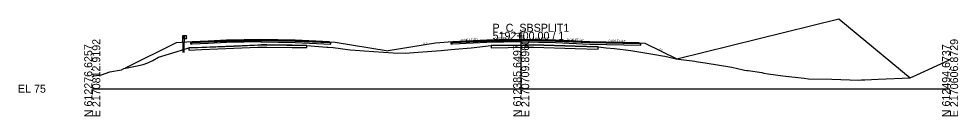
# Model space of a CAD drawing. Extents: x -26 to 1303, y -3010 to 12033.
# Drawn here: x -25.7 to 302.8, y 10490.3 to 10524.6 of the extents above; entities that cross this region are included whole.
import ezdxf

# ---------------------------------------------------------------- set-up
doc = ezdxf.new("R2010")
doc.units = 0
for name, color, linetype in [('RD_GPK_XS_Cell', 7, 'Continuous'), ('RD_PD_Final_TrvlWay', 7, 'Continuous'), ('RD_Sketch10', 7, 'Continuous'), ('RD_XS_Base', 7, 'Continuous'), ('RD_XS_ExGround', 7, 'Continuous'), ('RD_XS_ExPaveRet', 7, 'Continuous'), ('RD_XS_GR', 7, 'Continuous'), ('RD_XS_Greenside', 7, 'Continuous'), ('RD_XS_Pave', 7, 'Continuous'), ('RD_XS_PaveOvlay_CP', 7, 'Continuous'), ('RD_XS_TieSlope', 7, 'Continuous'), ('RD_XS_TX_Elev_EX', 7, 'Continuous'), ('RD_XS_TX_Elev_PR', 7, 'Continuous'), ('RD_XS_TX_Slope', 7, 'Continuous')]:
    doc.layers.add(name, color=color, linetype=linetype)

msp = doc.modelspace()

# ---------------------------------------------------------------- linework, layer by layer
at = {"layer": 'RD_GPK_XS_Cell'}
for p, q in [((150, 10500), (150, 10520)), ((0, 10500), (150, 10500)), ((150, 10500), (300, 10500))]:
    msp.add_line(p, q, dxfattribs=at)
at = {"layer": 'RD_PD_Final_TrvlWay'}
msp.add_lwpolyline([(32.13, 10512.68), (32.13, 10516.28), (31.63, 10516.24), (31.63, 10512.68)], dxfattribs=at)
at = {"layer": 'RD_Sketch10'}
msp.add_lwpolyline([(204.39, 10510.46), (261.07, 10524.58), (286.02, 10503.83)], dxfattribs=at)
at = {"layer": 'RD_XS_Base'}
for p, q in [((34.96, 10516.19), (40.51, 10516.41)), ((40.51, 10516.41), (46.96, 10516.67)), ((46.96, 10516.67), (53.12, 10516.79)), ((53.12, 10516.79), (58.96, 10516.91)), ((58.96, 10516.41), (53.12, 10516.29)), ((58.96, 10517), (58.96, 10517.07)), ((58.96, 10517.07), (58.96, 10516.76)), ((58.96, 10516.91), (58.96, 10517.07)), ((58.96, 10517.07), (58.96, 10516.41)), ((58.96, 10516.91), (58.96, 10517)), ((58.96, 10516.91), (58.96, 10516.68)), ((58.96, 10516.91), (58.96, 10516.41)), ((70.96, 10516.67), (58.96, 10516.91)), ((58.96, 10516.91), (58.96, 10516.91)), ((58.96, 10516.76), (58.96, 10516.41)), ((58.96, 10516.68), (58.96, 10516.41)), ((58.96, 10516.41), (58.96, 10516.41)), ((58.96, 10516.41), (58.96, 10516.41)), ((58.96, 10516.41), (70.96, 10516.17)), ((82.96, 10516.19), (70.96, 10516.67)), ((72.96, 10516.59), (72.96, 10516.59)), ((126, 10516.19), (138, 10516.67)), ((136, 10516.59), (136, 10516.59)), ((138, 10516.67), (150, 10516.91)), ((150, 10516.41), (138, 10516.17)), ((150, 10516.91), (150, 10517.07)), ((150, 10517.07), (150, 10516.41)), ((150, 10516.91), (150, 10516.91)), ((162, 10516.67), (150, 10516.91)), ((150, 10516.91), (150, 10516.91)), ((150, 10516.91), (150, 10516.41)), ((150, 10516.41), (150, 10516.41)), ((150, 10516.41), (162, 10516.17)), ((150, 10516.41), (150, 10516.41)), ((174, 10516.19), (162, 10516.67)), ((162, 10516.67), (162, 10516.67)), ((34.46, 10516.17), (34.68, 10516.18)), ((34.46, 10515.89), (34.46, 10516.17)), ((34.46, 10515.67), (34.46, 10515.89)), ((34.68, 10515.68), (34.46, 10515.67)), ((34.68, 10516.18), (34.96, 10516.19)), ((34.96, 10515.69), (34.68, 10515.68)), ((40.51, 10515.91), (34.96, 10515.69)), ((46.96, 10516.17), (40.51, 10515.91)), ((53.12, 10516.29), (46.96, 10516.17)), ((70.96, 10516.17), (83.46, 10515.67)), ((72.96, 10516.09), (72.96, 10516.09)), ((83.46, 10516.17), (82.96, 10516.19)), ((82.96, 10516.19), (82.96, 10516.19)), ((83.46, 10515.67), (83.46, 10516.17)), ((83.46, 10516.17), (83.46, 10516.17)), ((83.46, 10515.67), (83.46, 10515.67)), ((83.46, 10515.67), (83.46, 10515.67)), ((125.5, 10516.17), (126, 10516.19)), ((125.5, 10515.67), (125.5, 10516.17)), ((125.5, 10516.17), (125.5, 10516.17)), ((126, 10515.69), (125.5, 10515.67)), ((125.5, 10515.67), (125.5, 10515.67)), ((125.5, 10515.67), (125.5, 10515.67)), ((126, 10516.19), (126, 10516.19)), ((138, 10516.17), (126, 10515.69)), ((126, 10515.69), (126, 10515.69)), ((136, 10516.09), (136, 10516.09)), ((162, 10516.17), (162, 10516.17)), ((162, 10516.17), (174, 10515.69)), ((191.3, 10515.85), (174, 10516.19)), ((174, 10516.19), (174, 10516.19)), ((174, 10515.69), (174, 10515.69)), ((174, 10515.69), (191.8, 10515.34)), ((191.8, 10515.84), (191.3, 10515.85)), ((191.3, 10515.85), (191.3, 10515.85)), ((191.8, 10515.34), (191.8, 10515.84)), ((191.8, 10515.84), (191.8, 10515.84)), ((191.8, 10515.34), (191.8, 10515.34)), ((191.8, 10515.34), (191.8, 10515.34))]:
    msp.add_line(p, q, dxfattribs=at)
at = {"layer": 'RD_XS_ExGround'}
msp.add_lwpolyline([(0, 10504.22), (0.53, 10504.47), (3.21, 10504.91), (6.16, 10505.96), (10.24, 10506.67), (11.05, 10507.06), (15.14, 10507.95), (17.8, 10508.48), (19.41, 10509.13), (21.13, 10509.93), (23.18, 10511.04), (29.4, 10512.89), (33.81, 10514.33), (49.47, 10514.98), (59.16, 10515.39), (61.08, 10515.36), (75.08, 10515.17), (82.06, 10514.64), (82.48, 10514.61), (84.23, 10514.49), (86.82, 10514.07), (90.21, 10513.69), (92, 10513.5), (95.09, 10513.25), (105.19, 10512.54), (109.39, 10512.45), (113.99, 10512.87), (122, 10513.47), (123.02, 10513.5), (126.8, 10513.87), (132.55, 10514.4), (139.47, 10515.14), (151.38, 10515.32), (154.34, 10515.37), (168.93, 10514.92), (176.95, 10514.67), (179.7, 10514.38), (182.62, 10514.07), (188.36, 10513.47), (197.44, 10511.91), (199.42, 10511.55), (200.25, 10511.43), (203.78, 10510.56), (204.06, 10510.5), (210.7, 10509.64), (211.15, 10509.58), (211.92, 10509.44), (214.4, 10509.06), (223.7, 10507.52), (227.69, 10506.65), (228.09, 10506.54), (228.88, 10506.43), (229.43, 10506.34), (234.12, 10505.67), (234.88, 10505.5), (236.33, 10505.27), (241.55, 10504.49), (248.91, 10503.67), (250.54, 10503.5), (258.65, 10503.31), (268.1, 10503.05), (268.99, 10503.07), (270.22, 10503.14), (274.79, 10503.32), (286.02, 10503.83), (288.32, 10504.81), (298.31, 10509.39), (299.32, 10509.88), (300, 10510.21)], dxfattribs=at)
at = {"layer": 'RD_XS_ExPaveRet'}
for points in [[(61.08, 10515.36), (59.42, 10515.39), (59.16, 10515.39), (57.95, 10515.34), (49.47, 10514.98), (38.35, 10514.52), (33.81, 10514.33), (33.81, 10514), (33.81, 10513.58), (38.35, 10513.77), (49.47, 10514.23), (57.95, 10514.59), (59.16, 10514.64), (59.42, 10514.64), (61.08, 10514.61), (69.93, 10514.49), (75.08, 10514.42), (75.08, 10514.72), (75.08, 10515.17), (69.93, 10515.24), (61.08, 10515.36)], [(61.08, 10515.36), (59.42, 10515.39), (59.16, 10515.39), (57.95, 10515.34), (49.47, 10514.98), (38.35, 10514.52), (33.81, 10514.33), (33.81, 10514), (33.81, 10513.58), (38.35, 10513.77), (49.47, 10514.23), (57.95, 10514.59), (59.16, 10514.64), (59.42, 10514.64), (61.08, 10514.61), (69.93, 10514.49), (75.08, 10514.42), (75.08, 10514.72), (75.08, 10515.17), (69.93, 10515.24), (61.08, 10515.36)], [(176.95, 10514.67), (168.93, 10514.92), (168.93, 10514.92), (154.34, 10515.37), (154.34, 10515.37), (154.34, 10515.37), (154.34, 10515.37), (151.38, 10515.32), (151.38, 10515.32), (139.47, 10515.14), (139.47, 10515.14), (139.47, 10514.39), (151.38, 10514.57), (151.38, 10514.57), (154.34, 10514.62), (154.34, 10514.62), (154.34, 10514.62), (154.34, 10514.62), (168.93, 10514.17), (168.93, 10514.17), (176.95, 10513.92), (176.95, 10513.92), (176.95, 10513.92), (176.95, 10514.67), (176.95, 10514.67)], [(176.95, 10514.67), (168.93, 10514.92), (154.34, 10515.37), (151.38, 10515.32), (139.47, 10515.14), (139.47, 10514.39), (151.38, 10514.57), (154.34, 10514.62), (168.93, 10514.17), (176.95, 10513.92), (176.95, 10514.67)]]:
    msp.add_lwpolyline(points, dxfattribs=at)
at = {"layer": 'RD_XS_GR'}
for p, q in [((31.63, 10516.24), (31.63, 10518.68)), ((31.63, 10518.68), (31.88, 10518.68)), ((31.88, 10518.68), (32.13, 10518.68)), ((32.13, 10518.68), (32.13, 10516.28)), ((32.13, 10517.51), (32.13, 10518.68)), ((32.13, 10518.68), (32.79, 10518.68)), ((32.79, 10517.51), (32.13, 10517.51)), ((32.79, 10518.68), (32.79, 10517.51)), ((32.95, 10518.51), (32.79, 10518.68)), ((32.79, 10518.68), (32.79, 10518.01)), ((32.79, 10518.09), (32.91, 10518.22)), ((32.95, 10517.93), (32.79, 10518.09)), ((32.79, 10518.01), (32.79, 10517.51)), ((32.79, 10517.51), (32.91, 10517.64)), ((32.91, 10518.22), (33.07, 10518.39)), ((32.91, 10517.64), (33.07, 10517.8)), ((33.07, 10518.39), (32.95, 10518.51)), ((33.07, 10517.8), (32.95, 10517.93)), ((32.13, 10516.28), (31.63, 10516.24))]:
    msp.add_line(p, q, dxfattribs=at)
at = {"layer": 'RD_XS_Greenside'}
for p, q in [((84.96, 10516.35), (103.44, 10513.27)), ((29.32, 10516.06), (11.52, 10507.16)), ((120, 10516.03), (103.44, 10513.27)), ((193.3, 10516), (204.39, 10510.46))]:
    msp.add_line(p, q, dxfattribs=at)
at = {"layer": 'RD_XS_Pave'}
for p, q in [((40.51, 10516.73), (34.96, 10516.51)), ((40.51, 10516.57), (34.96, 10516.35)), ((34.96, 10516.35), (40.51, 10516.57)), ((34.96, 10516.51), (34.96, 10516.42)), ((34.96, 10516.42), (34.96, 10516.35)), ((34.96, 10516.19), (40.51, 10516.41)), ((34.96, 10516.35), (34.96, 10516.26)), ((46.96, 10516.99), (40.51, 10516.73)), ((46.96, 10516.83), (40.51, 10516.57)), ((40.51, 10516.57), (46.96, 10516.83)), ((40.51, 10516.41), (46.96, 10516.67)), ((53.12, 10517.11), (46.96, 10516.99)), ((53.12, 10516.95), (46.96, 10516.83)), ((46.96, 10516.83), (53.12, 10516.95)), ((46.96, 10516.67), (53.12, 10516.79)), ((58.96, 10517.23), (53.12, 10517.11)), ((58.96, 10517.07), (53.12, 10516.95)), ((53.12, 10516.95), (58.96, 10517.07)), ((53.12, 10516.79), (58.96, 10516.91)), ((70.96, 10516.99), (58.96, 10517.23)), ((58.96, 10517), (58.96, 10517.07)), ((58.96, 10517.07), (58.96, 10517)), ((58.96, 10516.91), (58.96, 10517.07)), ((58.96, 10517.07), (70.96, 10516.83)), ((70.96, 10516.83), (58.96, 10517.07)), ((58.96, 10517.07), (58.96, 10516.91)), ((58.96, 10516.91), (58.96, 10517)), ((58.96, 10517), (58.96, 10516.91)), ((58.96, 10516.91), (58.96, 10516.91)), ((58.96, 10516.91), (58.96, 10516.91)), ((58.96, 10516.91), (70.96, 10516.67)), ((82.96, 10516.51), (70.96, 10516.99)), ((70.96, 10516.83), (82.96, 10516.35)), ((82.96, 10516.35), (70.96, 10516.83)), ((70.96, 10516.67), (82.96, 10516.19)), ((72.96, 10516.91), (72.96, 10516.91)), ((72.96, 10516.75), (72.96, 10516.75)), ((72.96, 10516.75), (72.96, 10516.75)), ((72.96, 10516.59), (72.96, 10516.59)), ((82.96, 10516.35), (82.96, 10516.51)), ((82.96, 10516.51), (82.96, 10516.51)), ((82.96, 10516.35), (82.96, 10516.35)), ((82.96, 10516.35), (82.96, 10516.35)), ((82.96, 10516.19), (82.96, 10516.35)), ((82.96, 10516.35), (82.96, 10516.35)), ((138, 10516.99), (126, 10516.51)), ((138, 10516.83), (126, 10516.35)), ((126, 10516.35), (138, 10516.83)), ((126, 10516.19), (138, 10516.67)), ((126, 10516.51), (126, 10516.51)), ((126, 10516.51), (126, 10516.35)), ((126, 10516.35), (126, 10516.35)), ((126, 10516.35), (126, 10516.19)), ((126, 10516.35), (126, 10516.35)), ((126, 10516.35), (126, 10516.35)), ((136, 10516.91), (136, 10516.91)), ((136, 10516.75), (136, 10516.75)), ((136, 10516.75), (136, 10516.75)), ((136, 10516.59), (136, 10516.59)), ((150, 10517.23), (138, 10516.99)), ((150, 10517.07), (138, 10516.83)), ((138, 10516.83), (150, 10517.07)), ((138, 10516.67), (150, 10516.91)), ((162, 10516.99), (150, 10517.23)), ((150, 10516.91), (150, 10517.07)), ((150, 10517.07), (162, 10516.83)), ((162, 10516.83), (150, 10517.07)), ((150, 10517.07), (150, 10517.07)), ((150, 10517.07), (150, 10516.91)), ((150, 10516.91), (150, 10516.91)), ((150, 10516.91), (150, 10516.91)), ((150, 10516.91), (150, 10516.91)), ((150, 10516.91), (162, 10516.67)), ((174, 10516.51), (162, 10516.99)), ((162, 10516.99), (162, 10516.99)), ((162, 10516.83), (162, 10516.83)), ((162, 10516.83), (174, 10516.35)), ((174, 10516.35), (162, 10516.83)), ((162, 10516.83), (162, 10516.83)), ((162, 10516.67), (162, 10516.67)), ((162, 10516.67), (174, 10516.19)), ((191.3, 10516.16), (174, 10516.51)), ((174, 10516.51), (174, 10516.51)), ((174, 10516.35), (174, 10516.35)), ((174, 10516.35), (191.3, 10516)), ((191.3, 10516), (174, 10516.35)), ((174, 10516.35), (174, 10516.35)), ((34.96, 10516.26), (34.96, 10516.19)), ((82.96, 10516.19), (82.96, 10516.19)), ((82.96, 10516.19), (82.96, 10516.19)), ((126, 10516.19), (126, 10516.19)), ((126, 10516.19), (126, 10516.19)), ((174, 10516.19), (174, 10516.19)), ((174, 10516.19), (191.3, 10515.85)), ((191.3, 10516), (191.3, 10516.16)), ((191.3, 10516.16), (191.3, 10516.16)), ((191.3, 10516), (191.3, 10516)), ((191.3, 10516), (191.3, 10516)), ((191.3, 10515.85), (191.3, 10516)), ((191.3, 10516), (191.3, 10516)), ((191.3, 10515.85), (191.3, 10515.85)), ((191.3, 10515.85), (191.3, 10515.85))]:
    msp.add_line(p, q, dxfattribs=at)
at = {"layer": 'RD_XS_PaveOvlay_CP'}
for p, q in [((34.96, 10516.51), (46.96, 10516.99)), ((46.96, 10516.99), (58.96, 10517.23)), ((58.96, 10517.23), (70.96, 10516.99)), ((70.96, 10516.99), (82.96, 10516.51)), ((138, 10516.99), (126, 10516.51)), ((126, 10516.51), (126, 10516.51)), ((136, 10516.91), (136, 10516.91)), ((150, 10517.23), (138, 10516.99)), ((162, 10516.99), (150, 10517.23)), ((174, 10516.51), (162, 10516.99)), ((162, 10516.99), (162, 10516.99)), ((191.3, 10516.16), (174, 10516.51)), ((174, 10516.51), (174, 10516.51)), ((191.3, 10516.16), (191.3, 10516.16))]:
    msp.add_line(p, q, dxfattribs=at)
at = {"layer": 'RD_XS_TieSlope'}
for p, q in [((34.96, 10516.51), (29.32, 10516.06)), ((82.96, 10516.51), (84.96, 10516.35)), ((126, 10516.51), (120, 10516.03)), ((191.3, 10516.16), (193.3, 10516))]:
    msp.add_line(p, q, dxfattribs=at)

# ---------------------------------------------------------------- texts
at = {"layer": 'RD_GPK_XS_Cell'}
for s, p in [('5192+00.00 / 1', (140, 10517.2)), ('P_C_SBSPLIT1', (140, 10520)), ('EL 75', (-26, 10498.6))]:
    msp.add_text(s, height=2.8, dxfattribs=at).set_placement(p)
for s, p in [('E 2170812.9192', (2.8, 10490)), ('E 2170709.8960', (152.8, 10490)), ('E 2170606.8729', (302.8, 10490)), ('N 612276.6257', (0, 10490)), ('N 612385.6497', (150, 10490)), ('N 612494.6737', (300, 10490))]:
    msp.add_text(s, height=2.8, rotation=90, dxfattribs=at).set_placement(p)
at = {"layer": 'RD_XS_TX_Elev_EX'}
msp.add_text('90.30', height=0.6, rotation=90, dxfattribs=at).set_placement((149.7, 10517.93))
at = {"layer": 'RD_XS_TX_Elev_PR'}
msp.add_text('92.23', height=1, rotation=90, dxfattribs=at).set_placement((151.24, 10517.41))
at = {"layer": 'RD_XS_TX_Slope'}
for s, rotation, p in [('0.040 FT./FT.', 2.2906, (128.93, 10516.73)), ('0.020 FT./FT.', 1.1458, (140.74, 10517.23)), ('0.020 FT./FT.', 358.8542, (153.94, 10517.25)), ('0.040 FT./FT.', 357.7094, (165.94, 10516.93)), ('0.020 FT./FT.', 358.8542, (180.59, 10516.48)), ('6:1', 9.4623, (115.85, 10515.39)), ('2:1', 333.4349, (198.06, 10513.69))]:
    msp.add_text(s, height=0.75, rotation=rotation, dxfattribs=at).set_placement(p)

doc.saveas('drawing.dxf')
